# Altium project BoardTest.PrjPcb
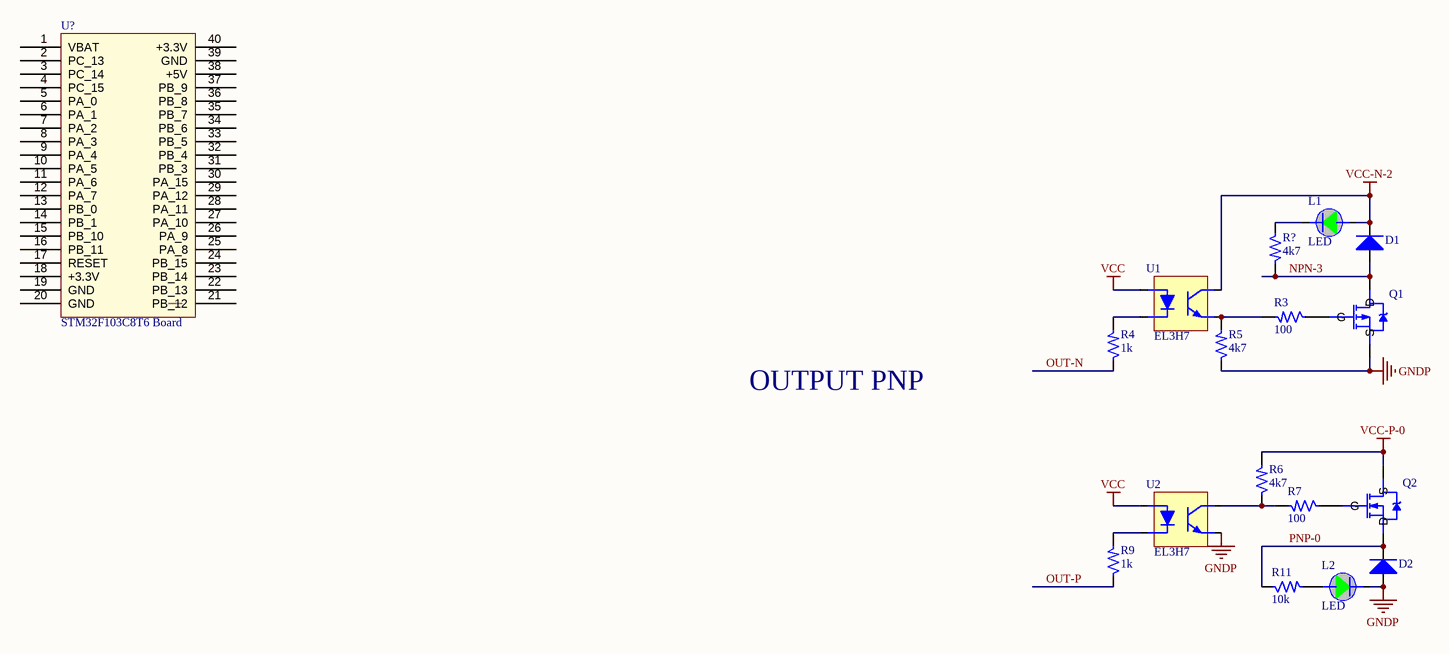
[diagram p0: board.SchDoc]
1 sheet, 17 parts. Net scope: global (net labels, ports and power ports of the same name join across sheets).
Board file: board.PcbDoc

## Sheet board.SchDoc
size A3

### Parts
D1  (no value)  [DIODE SS24 SMA]
D2  (no value)  [DIODE SS24 SMA]
L1  LED  [LED GREEN 0603 SMD]
L2  LED  [LED GREEN 0603 SMD]
Q1  MOSFET N  [AO3401 Mosfet P SOT23]  (value not drawn)
Q2  MOSFET P  [AO3401 Mosfet P SOT23]  (value not drawn)
R3  100  [RES 0603]
R4  1k  [RES 0603]
R5  4k7  [RES 0603]
R6  4k7  [RES 0603]
R7  100  [RES 0603]
R9  1k  [RES 0603]
R11  10k  [RES 0603]
R?  4k7  [RES 0603]
U1  EL3H7  [SSOP4]
U2  EL3H7  [SSOP4]
U?  STM32F103C8T6 Board  [STM32 Blue Pill]

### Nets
GNDP: D2.1(A) L2.2(Katot) Q1.2(S) R5.1 U2.3
VCC: U1.1 U2.1
VCC-N-2: D1.2(K) L1.1(anot) U1.4
VCC-P-0: Q2.1(S) R6.2
NPN-3: D1.1(A) Q1.1(D) R?.2
OUT-N: R4.1
OUT-P: R9.1
PNP-0: D2.2(K) Q2.2(D) R11.1
NetL1_2: L1.2(Katot) R?.1
NetL2_1: L2.1(anot) R11.2
NetQ1_3: Q1.3(G) R3.1
NetQ2_3: Q2.3(G) R7.1
NetR3_2: R3.2 R5.2 U1.3
NetR4_2: R4.2 U1.2
NetR6_1: R6.1 R7.2 U2.4
NetR9_2: R9.2 U2.2

Not connected (* = marked no-connect by the designer): U? 1(VBAT) 2(PC_13) 3(PC_14) 4(PC_15) 5(PA_0) 6(PA_1) 7(PA_2) 8(PA_3) 9(PA_4) 10(PA_5) 11(PA_6) 12(PA_7) 13(PB_0) 14(PB_1) 15(PB_10) 16(PB_11) 17(RESET) 18(+3.3V) 19(GND) 20(GND) 21(PB_12) 22(PB_13) 23(PB_14) 24(PB_15) 25(PA_8) 26(PA_9) 27(PA_10) 28(PA_11) 29(PA_12) 30(PA_15) 31(PB_3) 32(PB_4) 33(PB_5) 34(PB_6) 35(PB_7) 36(PB_8) 37(PB_9) 38(+5V) 39(GND) 40(+3.3V)

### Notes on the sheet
- OUTPUT PNP

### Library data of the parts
D1 D2 = diode SMA
L1 L2 = LED GREEN SMD
Q1 = MOSFET N AO3402
Q2 = MOSFET P AO3401
R3-R7 R9 R11 R? = res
